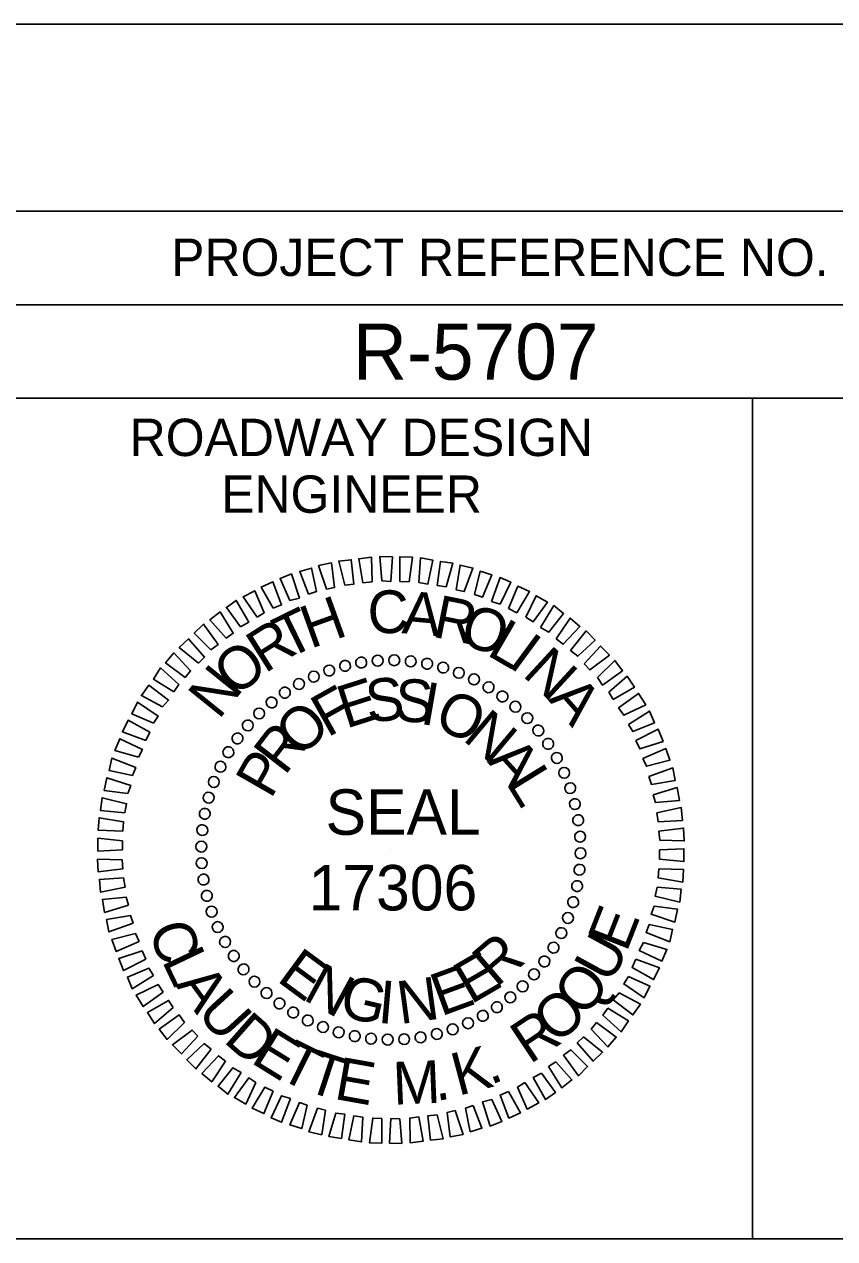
# Model space of a CAD drawing. Extents: x 573078 to 573116.9, y -55221.3 to -55199.3.
# Drawn here: x 573107.564 to 573109.734, y -55202.549 to -55199.298 of the extents above; entities that cross this region are included whole.
import ezdxf

# ---------------------------------------------------------------- set-up
doc = ezdxf.new("R2010")
doc.units = 0
for name, color, linetype in [('Prop Dimension', 7, 'Continuous'), ('Scratch_Level_1', 7, 'Continuous'), ('Sheet Data Field CELL', 7, 'Continuous'), ('Sheet Plot Border Inside CELL', 7, 'Continuous'), ('Sheet Profile CELL', 7, 'Continuous'), ('Sheet Profile Grid Minor CELL', 7, 'Continuous')]:
    doc.layers.add(name, color=color, linetype=linetype)

msp = doc.modelspace()

# ---------------------------------------------------------------- linework, layer by layer
at = {"layer": 'Prop Dimension'}
for p, q in [((573108.5105, -55201.0013), (573108.5105, -55201.0013)), ((573108.555, -55201.0004), (573108.555, -55201.0004)), ((573108.5996, -55201.0034), (573108.5996, -55201.0034)), ((573108.38, -55201.0277), (573108.38, -55201.0277)), ((573108.4225, -55201.0155), (573108.4225, -55201.0155)), ((573108.467, -55201.0074), (573108.467, -55201.0074)), ((573108.6432, -55201.0106), (573108.6432, -55201.0106)), ((573108.6857, -55201.0196), (573108.6857, -55201.0196)), ((573108.7283, -55201.0337), (573108.7283, -55201.0337)), ((573108.2999, -55201.0641), (573108.2999, -55201.0641)), ((573108.3395, -55201.0439), (573108.3395, -55201.0439)), ((573108.7688, -55201.052), (573108.7688, -55201.052)), ((573108.2614, -55201.0875), (573108.2614, -55201.0875)), ((573108.8081, -55201.0722), (573108.8081, -55201.0722)), ((573108.8446, -55201.0976), (573108.8446, -55201.0976)), ((573108.2261, -55201.1127), (573108.2261, -55201.1127)), ((573108.8801, -55201.1249), (573108.8801, -55201.1249)), ((573108.1925, -55201.1431), (573108.1925, -55201.1431)), ((573108.9114, -55201.1552), (573108.9114, -55201.1552)), ((573108.1622, -55201.1746), (573108.1622, -55201.1746)), ((573108.9418, -55201.1888), (573108.9418, -55201.1888)), ((573108.1349, -55201.2099), (573108.1349, -55201.2099)), ((573108.9672, -55201.2241), (573108.9672, -55201.2241)), ((573108.1095, -55201.2464), (573108.1095, -55201.2464)), ((573108.9904, -55201.2626), (573108.9904, -55201.2626)), ((573108.0893, -55201.286), (573108.0893, -55201.286)), ((573108.071, -55201.3265), (573108.071, -55201.3265)), ((573109.0106, -55201.3022), (573109.0106, -55201.3022)), ((573109.0268, -55201.3427), (573109.0268, -55201.3427)), ((573108.0569, -55201.369), (573108.0569, -55201.369)), ((573109.039, -55201.3852), (573109.039, -55201.3852)), ((573108.0479, -55201.4115), (573108.0479, -55201.4115)), ((573108.0407, -55201.4549), (573108.0407, -55201.4549)), ((573109.0471, -55201.4297), (573109.0471, -55201.4297)), ((573109.0532, -55201.4732), (573109.0532, -55201.4732)), ((573108.0377, -55201.4995), (573108.0377, -55201.4995)), ((573108.546, -55201.5087), (573108.546, -55201.5087)), ((573109.0543, -55201.5177), (573109.0543, -55201.5177)), ((573108.0386, -55201.544), (573108.0386, -55201.544)), ((573108.0447, -55201.5877), (573108.0447, -55201.5877)), ((573109.0511, -55201.5623), (573109.0511, -55201.5623)), ((573109.0442, -55201.6059), (573109.0442, -55201.6059)), ((573108.0528, -55201.6322), (573108.0528, -55201.6322)), ((573109.0349, -55201.6484), (573109.0349, -55201.6484)), ((573108.065, -55201.6748), (573108.065, -55201.6748)), ((573108.0812, -55201.7153), (573108.0812, -55201.7153)), ((573109.0208, -55201.691), (573109.0208, -55201.691)), ((573109.0025, -55201.7315), (573109.0025, -55201.7315)), ((573108.1014, -55201.7546), (573108.1014, -55201.7546)), ((573108.9823, -55201.7708), (573108.9823, -55201.7708)), ((573108.1248, -55201.7931), (573108.1248, -55201.7931)), ((573108.9571, -55201.8073), (573108.9571, -55201.8073)), ((573108.15, -55201.8287), (573108.15, -55201.8287)), ((573108.9296, -55201.8428), (573108.9296, -55201.8428)), ((573108.1804, -55201.862), (573108.1804, -55201.862)), ((573108.8993, -55201.8741), (573108.8993, -55201.8741)), ((573108.2119, -55201.8923), (573108.2119, -55201.8923)), ((573108.866, -55201.9045), (573108.866, -55201.9045)), ((573108.2472, -55201.9198), (573108.2472, -55201.9198)), ((573108.2837, -55201.945), (573108.2837, -55201.945)), ((573108.8304, -55201.9299), (573108.8304, -55201.9299)), ((573108.3233, -55201.9652), (573108.3233, -55201.9652)), ((573108.7526, -55201.9733), (573108.7526, -55201.9733)), ((573108.7919, -55201.9531), (573108.7919, -55201.9531)), ((573108.3638, -55201.9835), (573108.3638, -55201.9835)), ((573108.4063, -55201.9976), (573108.4063, -55201.9976)), ((573108.4488, -55202.0069), (573108.4488, -55202.0069)), ((573108.625, -55202.0098), (573108.625, -55202.0098)), ((573108.6695, -55202.0017), (573108.6695, -55202.0017)), ((573108.7121, -55201.9895), (573108.7121, -55201.9895)), ((573108.4922, -55202.0138), (573108.4922, -55202.0138)), ((573108.5368, -55202.017), (573108.5368, -55202.017)), ((573108.5813, -55202.0159), (573108.5813, -55202.0159))]:
    msp.add_line(p, q, dxfattribs=at)
for points in [[(573108.3739, -55200.811), (573108.3525, -55200.7473), (573108.3869, -55200.7401), (573108.395, -55200.806)], [(573108.4225, -55200.8), (573108.4063, -55200.7352), (573108.4396, -55200.732), (573108.4468, -55200.7968)], [(573108.4711, -55200.7939), (573108.4598, -55200.7291), (573108.4943, -55200.725), (573108.4954, -55200.7907)], [(573108.5217, -55200.7887), (573108.5165, -55200.723), (573108.5501, -55200.7239), (573108.546, -55200.7898)], [(573108.5703, -55200.7898), (573108.5703, -55200.7239), (573108.6036, -55200.725), (573108.5946, -55200.7907)], [(573108.6209, -55200.7928), (573108.625, -55200.7271), (573108.6583, -55200.7331), (573108.6452, -55200.7968)], [(573108.6695, -55200.8009), (573108.6785, -55200.7361), (573108.7121, -55200.7412), (573108.6938, -55200.804)], [(573108.2756, -55200.8405), (573108.2492, -55200.7817), (573108.2796, -55200.7696), (573108.301, -55200.8344)], [(573108.3253, -55200.8243), (573108.3019, -55200.7635), (573108.3334, -55200.7543), (573108.3464, -55200.8171)], [(573108.7211, -55200.8121), (573108.7312, -55200.7462), (573108.7656, -55200.7543), (573108.7424, -55200.8171)], [(573108.7697, -55200.8252), (573108.785, -55200.7624), (573108.8162, -55200.7725), (573108.791, -55200.8324)], [(573108.231, -55200.8616), (573108.1986, -55200.8049), (573108.2301, -55200.7907), (573108.2533, -55200.8526)], [(573108.8153, -55200.8434), (573108.8385, -55200.7797), (573108.8669, -55200.7919), (573108.8385, -55200.8506)], [(573108.8608, -55200.8627), (573108.8862, -55200.8029), (573108.9175, -55200.8171), (573108.8831, -55200.8738)], [(573108.143, -55200.9113), (573108.1055, -55200.8596), (573108.1318, -55200.8405), (573108.1653, -55200.8992)], [(573108.1876, -55200.8859), (573108.15, -55200.8312), (573108.1815, -55200.815), (573108.2067, -55200.8738)], [(573108.9074, -55200.8859), (573108.9348, -55200.8283), (573108.9652, -55200.8454), (573108.9267, -55200.8981)], [(573108.1046, -55200.9417), (573108.0609, -55200.8931), (573108.0884, -55200.8717), (573108.1237, -55200.9284)], [(573108.947, -55200.9134), (573108.9823, -55200.8546), (573109.0086, -55200.8758), (573108.9692, -55200.9255)], [(573108.0641, -55200.973), (573108.0195, -55200.9284), (573108.0438, -55200.9041), (573108.0832, -55200.9588)], [(573108.9884, -55200.9437), (573109.0259, -55200.8879), (573109.0523, -55200.9102), (573109.0077, -55200.9579)], [(573109.0268, -55200.975), (573109.0685, -55200.9224), (573109.0928, -55200.9467), (573109.0462, -55200.9903)], [(573108.0305, -55201.0085), (573107.979, -55200.9669), (573108.0042, -55200.9437), (573108.0467, -55200.9923)], [(573109.0633, -55201.0106), (573109.1069, -55200.9629), (573109.1312, -55200.9872), (573109.0786, -55201.0268)], [(573107.9952, -55201.047), (573107.9426, -55201.0074), (573107.9648, -55200.9811), (573108.0094, -55201.0288)], [(573109.0988, -55201.047), (573109.1454, -55201.0013), (573109.1666, -55201.0288), (573109.113, -55201.0673)], [(573107.9648, -55201.0855), (573107.9102, -55201.0511), (573107.9293, -55201.0216), (573107.9779, -55201.0661)], [(573107.9345, -55201.126), (573107.8778, -55201.0956), (573107.898, -55201.0673), (573107.9507, -55201.1078)], [(573109.1292, -55201.0864), (573109.1787, -55201.0439), (573109.1981, -55201.0733), (573109.1414, -55201.1057)], [(573109.1555, -55201.128), (573109.2091, -55201.0895), (573109.2284, -55201.1199), (573109.1697, -55201.1483)], [(573107.9102, -55201.1694), (573107.8523, -55201.1442), (573107.8676, -55201.1127), (573107.9223, -55201.1503)], [(573107.8899, -55201.216), (573107.8271, -55201.1928), (573107.8422, -55201.1613), (573107.9, -55201.1937)], [(573109.1819, -55201.1726), (573109.2386, -55201.137), (573109.2516, -55201.1685), (573109.194, -55201.1917)], [(573109.2021, -55201.216), (573109.2617, -55201.1856), (573109.275, -55201.218), (573109.2122, -55201.2383)], [(573107.8697, -55201.2605), (573107.8069, -55201.2423), (573107.8199, -55201.211), (573107.8807, -55201.2394)], [(573107.8544, -55201.3091), (573107.7916, -55201.2961), (573107.7988, -55201.2626), (573107.8625, -55201.288)], [(573109.2203, -55201.2637), (573109.282, -55201.2374), (573109.2932, -55201.2686), (573109.2305, -55201.2848)], [(573109.2365, -55201.3123), (573109.3013, -55201.2889), (573109.3074, -55201.3224), (573109.2435, -55201.3334)], [(573107.8413, -55201.3577), (573107.7785, -55201.3496), (573107.7855, -55201.3152), (573107.8494, -55201.3366)], [(573109.2487, -55201.3609), (573109.3124, -55201.3415), (573109.3184, -55201.376), (573109.2548, -55201.382)], [(573107.8332, -55201.4095), (573107.7684, -55201.4034), (573107.7725, -55201.369), (573107.8382, -55201.3852)], [(573107.828, -55201.4581), (573107.7623, -55201.4561), (573107.7644, -55201.4225), (573107.8301, -55201.4338)], [(573109.2577, -55201.4095), (573109.3236, -55201.3953), (573109.3265, -55201.4297), (573109.2617, -55201.4338)], [(573109.2638, -55201.4581), (573109.3297, -55201.45), (573109.3317, -55201.4844), (573109.2658, -55201.4824)], [(573107.8271, -55201.5087), (573107.7612, -55201.5116), (573107.7612, -55201.4772), (573107.8271, -55201.4844)], [(573109.2649, -55201.5087), (573109.3306, -55201.5056), (573109.3306, -55201.54), (573109.2649, -55201.533)], [(573107.828, -55201.5593), (573107.7623, -55201.5674), (573107.7603, -55201.533), (573107.826, -55201.535)], [(573107.8341, -55201.6079), (573107.7684, -55201.6221), (573107.7653, -55201.5877), (573107.8301, -55201.5836)], [(573109.2638, -55201.5593), (573109.3297, -55201.5614), (573109.3277, -55201.5947), (573109.2617, -55201.5836)], [(573109.2588, -55201.6079), (573109.3236, -55201.614), (573109.3196, -55201.6484), (573109.2536, -55201.6322)], [(573107.8433, -55201.6565), (573107.7794, -55201.6757), (573107.7734, -55201.6412), (573107.8373, -55201.6352)], [(573107.8555, -55201.7051), (573107.7907, -55201.7283), (573107.7846, -55201.695), (573107.8483, -55201.6838)], [(573109.2507, -55201.6595), (573109.3135, -55201.6676), (573109.3063, -55201.702), (573109.2426, -55201.6808)], [(573109.2374, -55201.7081), (573109.3002, -55201.7213), (573109.2932, -55201.7546), (573109.2293, -55201.7294)], [(573107.8717, -55201.7537), (573107.8098, -55201.7801), (573107.7988, -55201.7486), (573107.8616, -55201.7324)], [(573107.8899, -55201.8012), (573107.8301, -55201.8316), (573107.817, -55201.7992), (573107.8798, -55201.7789)], [(573109.2224, -55201.7567), (573109.2851, -55201.7749), (573109.2719, -55201.8064), (573109.2111, -55201.778)], [(573109.2021, -55201.8012), (573109.2649, -55201.8246), (573109.2496, -55201.8559), (573109.192, -55201.8235)], [(573107.9102, -55201.8449), (573107.8535, -55201.8802), (573107.8402, -55201.8489), (573107.898, -55201.8255)], [(573109.1819, -55201.8478), (573109.2395, -55201.8732), (573109.2244, -55201.9045), (573109.1697, -55201.8671)], [(573107.9365, -55201.8894), (573107.8827, -55201.9279), (573107.8636, -55201.8975), (573107.9223, -55201.8692)], [(573107.9628, -55201.9308), (573107.9131, -55201.9733), (573107.894, -55201.9441), (573107.9507, -55201.9117)], [(573109.1576, -55201.8914), (573109.2143, -55201.9218), (573109.194, -55201.9502), (573109.1414, -55201.9097)], [(573109.1272, -55201.9319), (573109.1819, -55201.9664), (573109.1625, -55201.9956), (573109.1139, -55201.9511)], [(573107.9932, -55201.9704), (573107.9466, -55202.0159), (573107.9252, -55201.9886), (573107.979, -55201.9502)], [(573109.0968, -55201.9704), (573109.1495, -55202.0098), (573109.1272, -55202.0361), (573109.0826, -55201.9886)], [(573108.0285, -55202.0069), (573107.9851, -55202.0543), (573107.9608, -55202.03), (573108.0134, -55201.9907)], [(573109.0613, -55202.0089), (573109.113, -55202.0503), (573109.0876, -55202.0737), (573109.0451, -55202.0251)], [(573108.065, -55202.0422), (573108.0236, -55202.0948), (573107.9993, -55202.0705), (573108.0458, -55202.0271)], [(573109.028, -55202.0442), (573109.0725, -55202.0888), (573109.0482, -55202.1131), (573109.0086, -55202.0584)], [(573108.1034, -55202.0737), (573108.0661, -55202.1293), (573108.0398, -55202.107), (573108.0843, -55202.0595)], [(573108.9875, -55202.0757), (573109.0309, -55202.1243), (573109.0037, -55202.1455), (573108.9681, -55202.0888)], [(573108.1451, -55202.1041), (573108.1095, -55202.1628), (573108.0832, -55202.1414), (573108.1228, -55202.0919)], [(573108.949, -55202.1061), (573108.9863, -55202.1576), (573108.96, -55202.177), (573108.9267, -55202.1182)], [(573108.1844, -55202.1313), (573108.1572, -55202.1891), (573108.1268, -55202.1718), (573108.1653, -55202.1191)], [(573108.9044, -55202.1313), (573108.9418, -55202.186), (573108.9105, -55202.2022), (573108.8851, -55202.1434)], [(573108.231, -55202.1547), (573108.2058, -55202.2143), (573108.1743, -55202.2001), (573108.2087, -55202.1434)], [(573108.2767, -55202.1738), (573108.2533, -55202.2377), (573108.2249, -55202.2256), (573108.2533, -55202.1668)], [(573108.8608, -55202.1556), (573108.8932, -55202.2123), (573108.8619, -55202.2265), (573108.8385, -55202.1648)], [(573108.3221, -55202.192), (573108.3071, -55202.2548), (573108.2756, -55202.2447), (573108.301, -55202.1851)], [(573108.3707, -55202.2053), (573108.3606, -55202.271), (573108.3262, -55202.2629), (573108.3496, -55202.2001)], [(573108.7181, -55202.2062), (573108.7393, -55202.2701), (573108.7049, -55202.2771), (573108.6968, -55202.2114)], [(573108.7667, -55202.1932), (573108.7899, -55202.2539), (573108.7586, -55202.2629), (573108.7454, -55202.2001)], [(573108.8162, -55202.177), (573108.8426, -55202.2357), (573108.8122, -55202.2478), (573108.791, -55202.183)], [(573108.4225, -55202.2163), (573108.4133, -55202.2811), (573108.38, -55202.2762), (573108.3982, -55202.2134)], [(573108.4711, -55202.2244), (573108.467, -55202.2904), (573108.4335, -55202.2843), (573108.4468, -55202.2204)], [(573108.5217, -55202.2276), (573108.5217, -55202.2933), (573108.4882, -55202.2924), (573108.4974, -55202.2265)], [(573108.5703, -55202.2285), (573108.5753, -55202.2944), (573108.542, -55202.2933), (573108.546, -55202.2276)], [(573108.6209, -55202.2235), (573108.632, -55202.2883), (573108.5975, -55202.2924), (573108.5966, -55202.2265)], [(573108.6695, -55202.2175), (573108.6857, -55202.2823), (573108.6522, -55202.2852), (573108.6452, -55202.2204)]]:
    msp.add_lwpolyline(points, close=True, dxfattribs=at)
for centre, major_axis in [((573108.4232, -55201.0159), (-0.0035, 0.0141)), ((573108.4666, -55201.007), (-0.0023, 0.0144)), ((573108.5106, -55201.002), (-0.001, 0.0145)), ((573108.5549, -55201.0009), (0.0003, 0.0146)), ((573108.5991, -55201.0036), (0.0015, 0.0145)), ((573108.6429, -55201.0101), (0.0028, 0.0143)), ((573108.686, -55201.0205), (0.004, 0.014)), ((573108.3394, -55201.0447), (-0.0059, 0.0133)), ((573108.3807, -55201.0284), (-0.0047, 0.0138)), ((573108.728, -55201.0345), (0.0052, 0.0136)), ((573108.7687, -55201.0522), (0.0064, 0.0131)), ((573108.2998, -55201.0645), (-0.0071, 0.0128)), ((573108.8076, -55201.0733), (0.0075, 0.0125)), ((573108.2264, -55201.114), (-0.0092, 0.0113)), ((573108.262, -55201.0876), (-0.0082, 0.0121)), ((573108.8445, -55201.0978), (0.0086, 0.0118)), ((573108.1932, -55201.1433), (-0.0101, 0.0105)), ((573108.8792, -55201.1254), (0.0096, 0.011)), ((573108.1627, -55201.1755), (-0.011, 0.0096)), ((573108.9113, -55201.1559), (0.0105, 0.0101)), ((573108.1351, -55201.2101), (-0.0118, 0.0086)), ((573108.9407, -55201.189), (0.0113, 0.0092)), ((573108.1107, -55201.2471), (-0.0125, 0.0075)), ((573108.9671, -55201.2246), (0.0121, 0.0082)), ((573108.9902, -55201.2624), (0.0128, 0.0071)), ((573108.0895, -55201.286), (-0.0131, 0.0064)), ((573109.01, -55201.3021), (0.0133, 0.0059)), ((573108.0719, -55201.3266), (-0.0136, 0.0052)), ((573109.0262, -55201.3433), (0.0138, 0.0047)), ((573108.0578, -55201.3687), (-0.014, 0.004)), ((573109.0388, -55201.3858), (0.0141, 0.0035)), ((573108.0475, -55201.4117), (-0.0143, 0.0028)), ((573109.0476, -55201.4292), (0.0144, 0.0023)), ((573108.0409, -55201.4556), (-0.0145, 0.0015)), ((573109.0527, -55201.4732), (0.0145, 0.001)), ((573108.0382, -55201.4998), (-0.0146, 0.0003)), ((573109.0538, -55201.5175), (0.0146, -0.0003)), ((573108.0394, -55201.5441), (-0.0145, -0.001)), ((573109.0511, -55201.5617), (0.0145, -0.0015)), ((573108.0444, -55201.5881), (-0.0144, -0.0023)), ((573109.0446, -55201.6056), (0.0143, -0.0028)), ((573108.0532, -55201.6315), (-0.0141, -0.0035)), ((573109.0342, -55201.6486), (0.014, -0.004)), ((573108.0658, -55201.674), (-0.0138, -0.0047)), ((573109.0202, -55201.6907), (0.0136, -0.0052)), ((573108.0821, -55201.7152), (-0.0133, -0.0059)), ((573109.0025, -55201.7313), (0.0131, -0.0064)), ((573108.1018, -55201.7549), (-0.0128, -0.0071)), ((573108.125, -55201.7926), (-0.0121, -0.0082)), ((573108.9813, -55201.7702), (0.0125, -0.0075)), ((573108.1513, -55201.8283), (-0.0113, -0.0092)), ((573108.9569, -55201.8072), (0.0118, -0.0086)), ((573108.1807, -55201.8614), (-0.0105, -0.0101)), ((573108.9293, -55201.8418), (0.011, -0.0096)), ((573108.2128, -55201.8919), (-0.0096, -0.011)), ((573108.8988, -55201.874), (0.0101, -0.0105)), ((573108.2475, -55201.9195), (-0.0086, -0.0118)), ((573108.83, -55201.9297), (0.0082, -0.0121)), ((573108.8656, -55201.9033), (0.0092, -0.0113)), ((573108.2844, -55201.944), (-0.0075, -0.0125)), ((573108.7922, -55201.9528), (0.0071, -0.0128)), ((573108.3234, -55201.9651), (-0.0064, -0.0131)), ((573108.364, -55201.9828), (-0.0052, -0.0136)), ((573108.7114, -55201.9888), (0.0047, -0.0138)), ((573108.7526, -55201.9726), (0.0059, -0.0133)), ((573108.406, -55201.9968), (-0.004, -0.014)), ((573108.4491, -55202.0072), (-0.0028, -0.0143)), ((573108.4929, -55202.0137), (-0.0015, -0.0145)), ((573108.5372, -55202.0164), (-0.0003, -0.0146)), ((573108.5814, -55202.0153), (0.001, -0.0145)), ((573108.6255, -55202.0103), (0.0023, -0.0144)), ((573108.6689, -55202.0014), (0.0035, -0.0141))]:
    msp.add_ellipse(centre, major_axis=major_axis, ratio=0.999708, dxfattribs=at)
at = {"layer": 'Scratch_Level_1'}
msp.add_line((573108.546, -55201.5087), (573108.546, -55201.5087), dxfattribs=at)
at = {"layer": 'Sheet Plot Border Inside CELL'}
msp.add_lwpolyline([(573112.0142, -55199.2984), (573078.0142, -55199.2984), (573078.0142, -55221.2984), (573112.0142, -55221.2984)], close=True, dxfattribs=at)
at = {"layer": 'Sheet Profile CELL'}
for p, q in [((573107.5142, -55200.0494), (573111.5142, -55200.0494)), ((573109.5142, -55200.2994), (573109.5142, -55202.5484))]:
    msp.add_line(p, q, dxfattribs=at)
for points in [[(573111.5142, -55199.7984), (573081.5142, -55199.7984), (573081.5142, -55220.7984), (573111.5142, -55220.7984)], [(573107.5142, -55199.7984), (573111.5142, -55199.7984), (573111.5142, -55200.2994), (573107.5142, -55200.2994)], [(573107.5142, -55200.2994), (573109.5142, -55200.2994), (573109.5142, -55202.5494), (573107.5142, -55202.5494)], [(573109.5142, -55200.2994), (573111.5142, -55200.2994), (573111.5142, -55202.5494), (573109.5142, -55202.5494)]]:
    msp.add_lwpolyline(points, close=True, dxfattribs=at)
at = {"layer": 'Sheet Profile Grid Minor CELL'}
msp.add_lwpolyline([(573107.4142, -55199.7984), (573107.6142, -55199.7984)], dxfattribs=at)

# ---------------------------------------------------------------- texts
at = {"layer": 'Prop Dimension'}
for s, height, rotation, p in [('H', 0.1144, 19.8207, (573108.3305, -55200.9707)), ('C', 0.1144, 1.0718, (573108.4844, -55200.9293)), ('A', 0.1144, 354.8222, (573108.5735, -55200.9282)), ('R', 0.1144, 348.5725, (573108.6545, -55200.9374)), ('T', 0.1144, 26.0703, (573108.2688, -55200.9991)), ('O', 0.1144, 342.3229, (573108.7253, -55200.9557)), ('R', 0.1144, 32.3199, (573108.2081, -55201.0376)), ('L', 0.1144, 329.8237, (573108.7994, -55200.9849)), ('I', 0.1144, 323.5741, (573108.8561, -55201.0144)), ('O', 0.1144, 38.5695, (573108.13, -55201.1015)), ('N', 0.1144, 317.3244, (573108.8954, -55201.0407)), ('N', 0.1144, 51.0688, (573108.0845, -55201.1622)), ('F', 0.1144, 29.3, (573108.3761, -55201.2088)), ('E', 0.1144, 17.6709, (573108.4256, -55201.1845)), ('S', 0.1144, 6.1833, (573108.4844, -55201.1683)), ('S', 0.1144, 358.4778, (573108.5564, -55201.1651)), ('I', 0.1144, 350.0931, (573108.6212, -55201.1703)), ('A', 0.1144, 311.0748, (573108.9654, -55201.1064)), ('O', 0.1144, 335.3611, (573108.6565, -55201.1773)), ('O', 0.1144, 43.5875, (573108.3041, -55201.2635)), ('N', 0.1144, 319.95, (573108.7355, -55201.2128)), ('R', 0.1144, 52.4166, (573108.2616, -55201.3121)), ('A', 0.1144, 312.2445, (573108.8023, -55201.2725)), ('P', 0.1144, 60.1222, (573108.2243, -55201.3748)), ('L', 0.1144, 301.6752, (573108.8529, -55201.3292)), ('SEAL', 0.1215, 0, (573108.371, -55201.468)), ('17306', 0.1215, 0, (573108.3255, -55201.6705)), ('E', 0.1144, 68.6635, (573109.1769, -55201.7848)), ('C', 0.1144, 287.4003, (573107.8971, -55201.718)), ('R', 0.1144, 40.7353, (573108.8277, -55201.8791)), ('U', 0.1144, 61.3078, (573109.1324, -55201.8698)), ('L', 0.1144, 295.5141, (573107.9315, -55201.805)), ('E', 0.1144, 323.6798, (573108.2373, -55201.8577)), ('E', 0.1144, 30.1214, (573108.7598, -55201.9236)), ('N', 0.1144, 331.3854, (573108.3073, -55201.9074)), ('E', 0.1144, 20.0411, (573108.6799, -55201.9549)), ('A', 0.1144, 306.1492, (573107.9671, -55201.8698)), ('G', 0.1144, 346.7965, (573108.4034, -55201.952)), ('N', 0.1144, 7.7341, (573108.5705, -55201.9751)), ('Q', 0.1144, 52.3928, (573109.0646, -55201.9601)), ('U', 0.1144, 312.3988, (573108.0227, -55201.9468)), ('I', 0.1144, 355.0405, (573108.5087, -55201.9711)), ('O', 0.1144, 39.8936, (573108.9877, -55202.0318)), ('D', 0.1144, 318.6484, (573108.0947, -55202.0208)), ('R', 0.1144, 33.6439, (573108.9177, -55202.0836)), ('E', 0.1144, 328.3523, (573108.1676, -55202.0764)), ('T', 0.1144, 333.6523, (573108.2393, -55202.1169)), ('T', 0.1144, 341.812, (573108.3122, -55202.1513)), ('K', 0.1144, 14.8951, (573108.7265, -55202.1675)), ('E', 0.1144, 349.8966, (573108.3912, -55202.1747)), ('M', 0.1144, 2.3958, (573108.5532, -55202.1909)), ('.', 0.1144, 21.1447, (573108.8124, -55202.1383)), ('.', 0.1144, 8.6454, (573108.6666, -55202.1808))]:
    msp.add_text(s, height=height, rotation=rotation, dxfattribs=at).set_placement(p)
at = {"layer": 'Sheet Data Field CELL'}
msp.add_text('R-5707', height=0.15, dxfattribs=at).set_placement((573108.4441, -55200.2497))
at = {"layer": 'Sheet Profile CELL'}
for s, height, p in [('PROJECT REFERENCE NO.', 0.100002, (573107.9574, -55199.9722)), ('ROADWAY DESIGN', 0.100002, (573107.8464, -55200.4542)), ('ENGINEER', 0.1, (573108.0914, -55200.6062))]:
    msp.add_text(s, height=height, dxfattribs=at).set_placement(p)

doc.saveas('drawing.dxf')
